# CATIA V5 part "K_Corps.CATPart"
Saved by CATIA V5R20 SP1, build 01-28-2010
Part number: corps
Publications: "Corps principal", "Ecart entre les barres du corps", "Longueur de barres du corps", "ecart entre barres de soutien", "longueur des barres de soutien", "niveau de la roue avant", "hauteur roue avant", "Point.1", "Point.2", "Point.3", "Point.4", "Droite.1", "Droite.2", "Point.5", "Point.6", "Point.7", "Point.8", "Droite.3", "Droite.4", "Droite.5", "Point.9", "Droite.6", "Point.10", "Droite.7", "Plan.1"
Bounding box of the stored display mesh (mm): x -50 to 720, y -400 to 400, z -100 to 50
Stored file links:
  G:\Khaled_CFAO_2011\ST2M\ST2M_GR1\cdurantin\cdurantin\Khaled\CAD_ThinkMOTION\K_Corps.CATPart
  G:\Khaled_CFAO_2011\ST2M\ST2M_GR1\cdurantin\cdurantin\Khaled\CAD_ThinkMOTION\K_Corps_Volume.CATPart
  G:\Khaled_CFAO_2011\ST2M\ST2M_GR1\cdurantin\cdurantin\Khaled\CAD_ThinkMOTION\K_Squelet.CATProduct
  G:\Khaled_CFAO_2011\ST2M\ST2M_GR1\cdurantin\cdurantin\Khaled\CAD_ThinkMOTION\K_PivotRoueAvant.CATPart
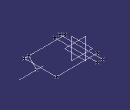
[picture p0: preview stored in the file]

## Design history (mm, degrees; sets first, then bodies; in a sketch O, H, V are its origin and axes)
Parameters
  `Ecart entre les barres du corps` = 100 mm
  `Longueur de barres du corps` = 800 mm
  `ecart entre barres de soutien` = 600 mm
  `longueur des barres de soutien` = 800 mm
  `niveau de la roue avant` = 850 mm
  `hauteur roue avant` = 100 mm
External parameters (linked from other documents)
  `External.Surepaisseur du tube` = 10 mm
  `External.Surepaisseur du tube` = 10 mm
  `External.diamètre des barres` = 40 mm
Set1
  Plane1: linked copy from another document
  Line1: linked copy from another document
Body1 (main body)
  Point1: type OnPlane, Support xy-plane, H 50 {= `Ecart entre les barres du corps` /2}, V 400 {= `Longueur de barres du corps` /2}, Direction (1, 0, 0)
  Point2: type OnPlane, Support xy-plane, H 50 {= `Ecart entre les barres du corps` /2}, V -400 {= -`Longueur de barres du corps` /2}, Direction (1, 0, 0)
  Point3: type OnPlane, Support xy-plane, H -50 {= -`Ecart entre les barres du corps` /2}, V 400 {= `Longueur de barres du corps` /2}, Direction (1, 0, 0)
  Point4: type OnPlane, Support xy-plane, H -50 {= -`Ecart entre les barres du corps` /2}, V -400 {= -`Longueur de barres du corps` /2}, Direction (1, 0, 0)
  Line2: type PtPt, FirstPoint Point1, SecondPoint Point2
  Line3: type PtPt, FirstPoint Point3, SecondPoint Point4
  Point5: (-50 {= -`Ecart entre les barres du corps` /2}, 300 {= `ecart entre barres de soutien` /2}, 50 {= `External.Surepaisseur du tube` +`External.diamètre des barres`})
  Point6: (-50 {= -`Ecart entre les barres du corps` /2}, -300 {= -`ecart entre barres de soutien` /2}, 50 {= `External.Surepaisseur du tube` +`External.diamètre des barres`})
  Point7: (720 {= `longueur des barres de soutien` -`longueur des barres de soutien` /10}, 300 {= `ecart entre barres de soutien` /2}, 50 {= `External.Surepaisseur du tube` +`External.diamètre des barres`})
  Point8: (720 {= `longueur des barres de soutien` -`longueur des barres de soutien` /10}, -300 {= -`ecart entre barres de soutien` /2}, 50 {= `External.Surepaisseur du tube` +`External.diamètre des barres`})
  Line4: type PtPt, FirstPoint Point6, SecondPoint Point8
  Line5: type PtPt, FirstPoint Point5, SecondPoint Point7
  Line6: type PtPt, FirstPoint Point7, SecondPoint Point8
  Point9: (640 {= `longueur des barres de soutien` -`longueur des barres de soutien` /5}, -300 {= -`ecart entre barres de soutien` /2}, 50 {= `External.Surepaisseur du tube` +`External.diamètre des barres`})
  Line7: type PtPt, FirstPoint Point9, SecondPoint Point8
  Point10: (640 {= `longueur des barres de soutien` -`longueur des barres de soutien` /5}, -150 {= -`ecart entre barres de soutien` /2+(`External.Surepaisseur du tube` +`External.diamètre des barres` +`hauteur roue avant` )}, -100 {= -`hauteur roue avant`})
  Line8: type PtPt, FirstPoint Point10, SecondPoint Point9
  Plane2: type Angle, RefPlane Plane1, Direction Line1, Angle 90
